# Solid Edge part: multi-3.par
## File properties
Author: Deepak Maini
Template: normal.par
Last saved by: CADCIM
Revision: 6
Application: Solid Edge
Accuracy: 0.99
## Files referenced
..\multi-cutout.asm
ED:\sld-edg-15\cd-models\c09-sld-edg-15\figure28-8&29\multi-cutout.asm
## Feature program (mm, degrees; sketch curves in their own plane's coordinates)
sketch for "unnamed Protrusion 1" plane through (0, 0, 0) normal (0, 0, 1) x-axis (1, 0, 0)
  circle centre (0, 0) radius 37.9639
extrude "unnamed Protrusion 1" add finite 26.55 along +normal
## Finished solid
Body 1: solid body, 3 faces, 2 edges, 0 vertices.
  Faces by surface: plane 2, cylinder 1
  Edges by curve: circle 2
Bounding box of the edges (mm): 75.928 x 75.928 x 26.550, from (-37.9639, -37.9639, 0) to (37.9639, 37.9639, 26.55).
Cylindrical faces by radius (mm): R37.9639 x1
Planar faces by outward normal: +z 1, -z 1
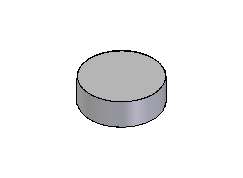
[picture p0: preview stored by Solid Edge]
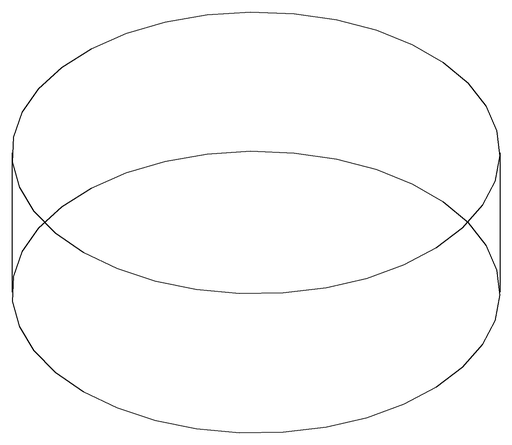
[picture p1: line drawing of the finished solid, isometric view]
